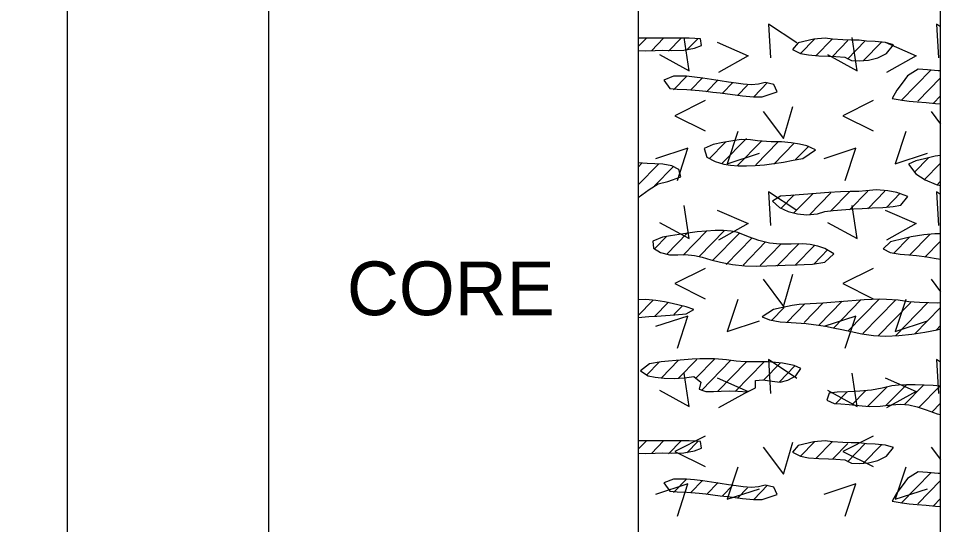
# Model space of a CAD drawing. Extents: x 0 to 0.833, y -0.323 to 0.608.
# Drawn here: x 0.719 to 0.8333, y -0.1987 to -0.1358 of the extents above; entities that cross this region are included whole.
import ezdxf

# ---------------------------------------------------------------- set-up
doc = ezdxf.new("R2010")
doc.units = 0

msp = doc.modelspace()

# ---------------------------------------------------------------- linework, layer by layer
for points in [[(0, -0.32328), (0.83333, -0.32328), (0.83333, 0.60833), (0, 0.60833)], [(0.79583, -0.13982), (0.79676, -0.13983), (0.79792, -0.13981), (0.79882, -0.13977), (0.79992, -0.13982), (0.80151, -0.13977), (0.80282, -0.13952), (0.80367, -0.1392), (0.80354, -0.13836), (0.80216, -0.13827), (0.79583, -0.13827)], [(0.81822, -0.14047), (0.81944, -0.14052), (0.82033, -0.14056), (0.82145, -0.14063), (0.82229, -0.14105), (0.82324, -0.14109), (0.82438, -0.14099), (0.82555, -0.1407), (0.82662, -0.14019), (0.82749, -0.1391), (0.82651, -0.13879), (0.82524, -0.13869), (0.82413, -0.13863), (0.82324, -0.13852), (0.82226, -0.1385), (0.82121, -0.13848), (0.81995, -0.13839), (0.81902, -0.13827), (0.81761, -0.13841), (0.81566, -0.13885), (0.81496, -0.13969), (0.81598, -0.14018), (0.81695, -0.14036)], [(0.83305, -0.14232), (0.83171, -0.14221), (0.83054, -0.14211), (0.82925, -0.14293), (0.82857, -0.14384), (0.82792, -0.14473), (0.82735, -0.14575), (0.82858, -0.14598), (0.82945, -0.14608), (0.83045, -0.14618), (0.83155, -0.14627), (0.83272, -0.14637), (0.83333, -0.14642), (0.83333, -0.14233)], [(0.80066, -0.14462), (0.80188, -0.14463), (0.80339, -0.14476), (0.80423, -0.14485), (0.8051, -0.14496), (0.806, -0.14508), (0.80692, -0.1452), (0.80784, -0.14532), (0.80875, -0.14543), (0.81014, -0.14557), (0.81119, -0.14556), (0.81222, -0.14522), (0.81308, -0.14493), (0.81267, -0.14403), (0.8116, -0.14378), (0.81075, -0.14398), (0.80989, -0.14406), (0.80885, -0.14398), (0.80799, -0.14387), (0.80703, -0.14373), (0.806, -0.14356), (0.80492, -0.1434), (0.80384, -0.14324), (0.8028, -0.14311), (0.80182, -0.14301), (0.8002, -0.14301), (0.79901, -0.14348), (0.79974, -0.14452)], [(0.81233, -0.15113), (0.81063, -0.15101), (0.80977, -0.15088), (0.8086, -0.15087), (0.80755, -0.15101), (0.80632, -0.15121), (0.80513, -0.15146), (0.80403, -0.15198), (0.80436, -0.15304), (0.80536, -0.1536), (0.80647, -0.1539), (0.8073, -0.15405), (0.80824, -0.15413), (0.80926, -0.15414), (0.81035, -0.15409), (0.81149, -0.15398), (0.81267, -0.15384), (0.81386, -0.15365), (0.81506, -0.15344), (0.81625, -0.15321), (0.81783, -0.15213), (0.81673, -0.15163), (0.81585, -0.15142), (0.8148, -0.15127), (0.81361, -0.15116)], [(0.83265, -0.15294), (0.83136, -0.15325), (0.83028, -0.15352), (0.82934, -0.15392), (0.83026, -0.15512), (0.83142, -0.15588), (0.83279, -0.15646), (0.83333, -0.15656), (0.83333, -0.15285)], [(0.79583, -0.15804), (0.79719, -0.15705), (0.79831, -0.15635), (0.79951, -0.15607), (0.80111, -0.15547), (0.80086, -0.15459), (0.80002, -0.15411), (0.79889, -0.15392), (0.79791, -0.15389), (0.79694, -0.15383), (0.79583, -0.15375)], [(0.82537, -0.15709), (0.82408, -0.15724), (0.82319, -0.1573), (0.82214, -0.15732), (0.82091, -0.15736), (0.81947, -0.15745), (0.81792, -0.15757), (0.81632, -0.15769), (0.81475, -0.15779), (0.81348, -0.15789), (0.81247, -0.15853), (0.81337, -0.15929), (0.81444, -0.15979), (0.81561, -0.16008), (0.81675, -0.16019), (0.81807, -0.16007), (0.81896, -0.1598), (0.82003, -0.15965), (0.82157, -0.15953), (0.82253, -0.15947), (0.82362, -0.15942), (0.82483, -0.15935), (0.82618, -0.15929), (0.82745, -0.15918), (0.82842, -0.159), (0.82927, -0.15795), (0.82791, -0.15743), (0.82679, -0.15723)], [(0.79885, -0.163), (0.79763, -0.16346), (0.79773, -0.16436), (0.79859, -0.16488), (0.7997, -0.16518), (0.80074, -0.16517), (0.80165, -0.16515), (0.80281, -0.16524), (0.80377, -0.16545), (0.80486, -0.1658), (0.80606, -0.16609), (0.80751, -0.16637), (0.80905, -0.16655), (0.81052, -0.16658), (0.81177, -0.16652), (0.81289, -0.16648), (0.81408, -0.16645), (0.81553, -0.16641), (0.81642, -0.16638), (0.81745, -0.16635), (0.81897, -0.16608), (0.82011, -0.16504), (0.81896, -0.16437), (0.8181, -0.16411), (0.81717, -0.16391), (0.81626, -0.1638), (0.81479, -0.16386), (0.81343, -0.16386), (0.8121, -0.16371), (0.8108, -0.16341), (0.80953, -0.16295), (0.8082, -0.1624), (0.80736, -0.16224), (0.8064, -0.16216), (0.80536, -0.16216), (0.80427, -0.16222), (0.80314, -0.16233), (0.80201, -0.16248), (0.8009, -0.16264), (0.79984, -0.16282)], [(0.83263, -0.16256), (0.83126, -0.16269), (0.82969, -0.16296), (0.82883, -0.16313), (0.82712, -0.16354), (0.82623, -0.16441), (0.82708, -0.1649), (0.82831, -0.16509), (0.82941, -0.16516), (0.83033, -0.16524), (0.83165, -0.16543), (0.83253, -0.16557), (0.83333, -0.16571), (0.83333, -0.16256)], [(0.79583, -0.17296), (0.79715, -0.17285), (0.79814, -0.17278), (0.79922, -0.1727), (0.80039, -0.17261), (0.80179, -0.17249), (0.80275, -0.17198), (0.80179, -0.17164), (0.80091, -0.17142), (0.80003, -0.1712), (0.79909, -0.17099), (0.79803, -0.17083), (0.79677, -0.17073), (0.79583, -0.17075)], [(0.82816, -0.17521), (0.82978, -0.17504), (0.83137, -0.17479), (0.8329, -0.17447), (0.83333, -0.17437), (0.83333, -0.17113), (0.83295, -0.17116), (0.83188, -0.17114), (0.83071, -0.17109), (0.82938, -0.17099), (0.82807, -0.17082), (0.82662, -0.1707), (0.82576, -0.17069), (0.82484, -0.17072), (0.82387, -0.17077), (0.82286, -0.17084), (0.82182, -0.17092), (0.82077, -0.171), (0.81973, -0.17109), (0.81872, -0.17116), (0.81715, -0.17126), (0.81579, -0.17135), (0.81491, -0.17148), (0.81357, -0.17176), (0.8126, -0.17197), (0.81121, -0.17289), (0.8121, -0.17325), (0.81345, -0.1735), (0.81479, -0.17359), (0.81668, -0.17369), (0.81818, -0.17389), (0.81905, -0.17404), (0.82, -0.17422), (0.82107, -0.17443), (0.82225, -0.17468), (0.82357, -0.17497), (0.82501, -0.1752), (0.82656, -0.17527)], [(0.79708, -0.18019), (0.79794, -0.18037), (0.79904, -0.18048), (0.80028, -0.18051), (0.80156, -0.18046), (0.80274, -0.1803), (0.80361, -0.18097), (0.80338, -0.18186), (0.80422, -0.18213), (0.80517, -0.18215), (0.80613, -0.1821), (0.8072, -0.18206), (0.80818, -0.1821), (0.80939, -0.18217), (0.81037, -0.1817), (0.81038, -0.18076), (0.8113, -0.18069), (0.81244, -0.18088), (0.81346, -0.18099), (0.81438, -0.18073), (0.81539, -0.18019), (0.81601, -0.17928), (0.81517, -0.1789), (0.81374, -0.17863), (0.81285, -0.17853), (0.81187, -0.17848), (0.81, -0.17847), (0.8091, -0.17846), (0.808, -0.17838), (0.80678, -0.17823), (0.8053, -0.1781), (0.80443, -0.17808), (0.80349, -0.1781), (0.80251, -0.17814), (0.80152, -0.1782), (0.80054, -0.17828), (0.79959, -0.17837), (0.7987, -0.17847), (0.79722, -0.17869), (0.79614, -0.17957)], [(0.83241, -0.18141), (0.83129, -0.18134), (0.83017, -0.18131), (0.8291, -0.1813), (0.82811, -0.18134), (0.82728, -0.18143), (0.82608, -0.18173), (0.82476, -0.18196), (0.8233, -0.18209), (0.82183, -0.18218), (0.82051, -0.18224), (0.81951, -0.18233), (0.81922, -0.1832), (0.82013, -0.18362), (0.82097, -0.18367), (0.822, -0.18377), (0.82318, -0.1839), (0.82448, -0.18399), (0.82584, -0.18396), (0.82719, -0.1838), (0.82836, -0.18373), (0.8294, -0.18381), (0.83043, -0.18404), (0.83156, -0.18444), (0.83291, -0.18493), (0.83333, -0.185), (0.83333, -0.18148)], [(0.79583, -0.18982), (0.79676, -0.18983), (0.79792, -0.18981), (0.79882, -0.18977), (0.79992, -0.18982), (0.80151, -0.18977), (0.80282, -0.18952), (0.80367, -0.1892), (0.80354, -0.18836), (0.80216, -0.18827), (0.79583, -0.18827)], [(0.81822, -0.19047), (0.81944, -0.19052), (0.82033, -0.19056), (0.82145, -0.19063), (0.82229, -0.19105), (0.82324, -0.19109), (0.82438, -0.19099), (0.82555, -0.1907), (0.82662, -0.19019), (0.82749, -0.1891), (0.82651, -0.18879), (0.82524, -0.18869), (0.82413, -0.18863), (0.82324, -0.18852), (0.82226, -0.1885), (0.82121, -0.18848), (0.81995, -0.18839), (0.81902, -0.18827), (0.81761, -0.18841), (0.81566, -0.18885), (0.81496, -0.18969), (0.81598, -0.19018), (0.81695, -0.19036)], [(0.83305, -0.19232), (0.83171, -0.19221), (0.83054, -0.19211), (0.82925, -0.19293), (0.82857, -0.19384), (0.82792, -0.19473), (0.82735, -0.19575), (0.82858, -0.19598), (0.82945, -0.19608), (0.83045, -0.19618), (0.83155, -0.19627), (0.83272, -0.19637), (0.83333, -0.19642), (0.83333, -0.19233)], [(0.80066, -0.19462), (0.80188, -0.19463), (0.80339, -0.19476), (0.80423, -0.19485), (0.8051, -0.19496), (0.806, -0.19508), (0.80692, -0.1952), (0.80784, -0.19532), (0.80875, -0.19543), (0.81014, -0.19557), (0.81119, -0.19556), (0.81222, -0.19522), (0.81308, -0.19493), (0.81267, -0.19403), (0.8116, -0.19378), (0.81075, -0.19398), (0.80989, -0.19406), (0.80885, -0.19398), (0.80799, -0.19387), (0.80703, -0.19373), (0.806, -0.19356), (0.80492, -0.1934), (0.80384, -0.19324), (0.8028, -0.19311), (0.80182, -0.19301), (0.8002, -0.19301), (0.79901, -0.19348), (0.79974, -0.19452)]]:
    msp.add_lwpolyline(points, close=True)
for points in [[(0.725, 0.55417), (0.725, -0.28575)], [(0.75, 0.55417), (0.75, -0.28575)], [(0.75, 0.55417), (0.75, -0.28575)], [(0.79583, 0.55417), (0.79583, -0.28575)], [(0.725, 0.54167), (0.725, -0.28575)], [(0.83333, -0.28575), (0.83333, 0.50165)], [(0.81551, -0.13884), (0.81201, -0.13653), (0.81226, -0.14071)], [(0.83333, -0.13685), (0.83284, -0.13653), (0.83309, -0.14071)], [(0.79583, -0.1393), (0.79681, -0.1383)], [(0.79898, -0.13828), (0.79747, -0.13983)], [(0.79847, -0.14032), (0.80215, -0.14232), (0.80153, -0.1382)], [(0.80116, -0.13827), (0.79959, -0.13987)], [(0.80328, -0.13831), (0.80188, -0.13974)], [(0.8193, -0.14032), (0.82299, -0.14232), (0.82236, -0.1382)], [(0.80562, -0.13878), (0.80946, -0.14046), (0.80581, -0.14252)], [(0.8177, -0.13841), (0.81596, -0.14019)], [(0.81988, -0.13839), (0.81785, -0.14047)], [(0.82185, -0.13858), (0.81997, -0.14051)], [(0.824, -0.13859), (0.82178, -0.14087)], [(0.82601, -0.13875), (0.82378, -0.14103)], [(0.82645, -0.13878), (0.83029, -0.14046), (0.82664, -0.14252)], [(0.83217, -0.14219), (0.82844, -0.14601)], [(0.80188, -0.14297), (0.8002, -0.14469)], [(0.8038, -0.14321), (0.80237, -0.14467)], [(0.80575, -0.14343), (0.80429, -0.14492)], [(0.80758, -0.14376), (0.80627, -0.14511)], [(0.81188, -0.14378), (0.81016, -0.14554)], [(0.83333, -0.14321), (0.83052, -0.14609)], [(0.80941, -0.1441), (0.80816, -0.14538)], [(0.80412, -0.14603), (0.80038, -0.14791), (0.80412, -0.14978)], [(0.82496, -0.14603), (0.82121, -0.14791), (0.82496, -0.14978)], [(0.83333, -0.14543), (0.83245, -0.14633)], [(0.81134, -0.14738), (0.81384, -0.15075), (0.81503, -0.14675)], [(0.83217, -0.14738), (0.83333, -0.14894)], [(0.80626, -0.15381), (0.80928, -0.15071)], [(0.80818, -0.14987), (0.80687, -0.15387), (0.81087, -0.15255)], [(0.82901, -0.14987), (0.8277, -0.15387), (0.8317, -0.15255)], [(0.80069, -0.15595), (0.802, -0.15195), (0.798, -0.15326)], [(0.80465, -0.15324), (0.80667, -0.15117)], [(0.80809, -0.15414), (0.81111, -0.15105)], [(0.81041, -0.15398), (0.81318, -0.15115)], [(0.81264, -0.1539), (0.81518, -0.1513)], [(0.81536, -0.15333), (0.81699, -0.15167)], [(0.82152, -0.15595), (0.82284, -0.15195), (0.81884, -0.15326)], [(0.8301, -0.15491), (0.83184, -0.15312)], [(0.7963, -0.15379), (0.79583, -0.15427)], [(0.79834, -0.15392), (0.79583, -0.15649)], [(0.79786, -0.15662), (0.80023, -0.15419)], [(0.83131, -0.15588), (0.83333, -0.15381)], [(0.83285, -0.15651), (0.83333, -0.15602)], [(0.81551, -0.15967), (0.81201, -0.15736), (0.81226, -0.16155)], [(0.81519, -0.15772), (0.81354, -0.15942)], [(0.81514, -0.15998), (0.81748, -0.15759)], [(0.81709, -0.1602), (0.81974, -0.15749)], [(0.8197, -0.15975), (0.82203, -0.15735)], [(0.82202, -0.15958), (0.8243, -0.15725)], [(0.82431, -0.15945), (0.82644, -0.15726)], [(0.82663, -0.15928), (0.82834, -0.15753)], [(0.83333, -0.15768), (0.83284, -0.15736), (0.83309, -0.16155)], [(0.79847, -0.16116), (0.80215, -0.16316), (0.80153, -0.15903)], [(0.80562, -0.15961), (0.80946, -0.16129), (0.80581, -0.16336)], [(0.8193, -0.16116), (0.82299, -0.16316), (0.82236, -0.15903)], [(0.82645, -0.15961), (0.83029, -0.16129), (0.82664, -0.16336)], [(0.80142, -0.1652), (0.8043, -0.16225)], [(0.80653, -0.16217), (0.8034, -0.16539)], [(0.79938, -0.16287), (0.79786, -0.16442)], [(0.79933, -0.16513), (0.80195, -0.16244)], [(0.80506, -0.16589), (0.8084, -0.16247)], [(0.80997, -0.16307), (0.80675, -0.16638)], [(0.82751, -0.16502), (0.82945, -0.16303)], [(0.83203, -0.16261), (0.82949, -0.16521)], [(0.83138, -0.16548), (0.83333, -0.16348)], [(0.81164, -0.16358), (0.80884, -0.16644)], [(0.81353, -0.16386), (0.81094, -0.16651)], [(0.81303, -0.16658), (0.81579, -0.16375)], [(0.81534, -0.16642), (0.81768, -0.16402)], [(0.8176, -0.16632), (0.81934, -0.16453)], [(0.83333, -0.1657), (0.83333, -0.16569)], [(0.80412, -0.16687), (0.80038, -0.16874), (0.80412, -0.17062)], [(0.82496, -0.16687), (0.82121, -0.16874), (0.82496, -0.17062)], [(0.81134, -0.16821), (0.81384, -0.17158), (0.81503, -0.16758)], [(0.83217, -0.16821), (0.83333, -0.16977)], [(0.79765, -0.17085), (0.79583, -0.17271)], [(0.7996, -0.17106), (0.79786, -0.17284)], [(0.80818, -0.1707), (0.80687, -0.1747), (0.81087, -0.17339)], [(0.8143, -0.17352), (0.8165, -0.17127)], [(0.8164, -0.17359), (0.81879, -0.17114)], [(0.81829, -0.17387), (0.82114, -0.17094)], [(0.82004, -0.17429), (0.82346, -0.17078)], [(0.82569, -0.1707), (0.82184, -0.17465)], [(0.82775, -0.1708), (0.8237, -0.17495)], [(0.82964, -0.17108), (0.82557, -0.17526)], [(0.82901, -0.1707), (0.8277, -0.1747), (0.8317, -0.17339)], [(0.83173, -0.17115), (0.82774, -0.17524)], [(0.8013, -0.17154), (0.80027, -0.17259)], [(0.81392, -0.1717), (0.81235, -0.17331)], [(0.83333, -0.17173), (0.83012, -0.17502)], [(0.80069, -0.17678), (0.802, -0.17278), (0.798, -0.17409)], [(0.82152, -0.17678), (0.82284, -0.17278), (0.81884, -0.17409)], [(0.83281, -0.17447), (0.83333, -0.17394)], [(0.79871, -0.18045), (0.80085, -0.17825)], [(0.80083, -0.18049), (0.80311, -0.17815)], [(0.80534, -0.17807), (0.80299, -0.18049)], [(0.80367, -0.182), (0.80732, -0.17826)], [(0.81551, -0.18051), (0.81201, -0.17819), (0.81226, -0.18238)], [(0.83333, -0.17852), (0.83284, -0.17819), (0.83309, -0.18238)], [(0.79844, -0.17851), (0.79691, -0.18008)], [(0.80571, -0.18212), (0.80924, -0.17851)], [(0.81142, -0.17849), (0.80785, -0.18214)], [(0.81141, -0.18071), (0.81348, -0.17859)], [(0.81528, -0.17895), (0.81331, -0.18097)], [(0.79847, -0.18199), (0.80215, -0.18399), (0.80153, -0.17986)], [(0.80562, -0.18044), (0.80946, -0.18213), (0.80581, -0.18419)], [(0.8193, -0.18199), (0.82299, -0.18399), (0.82236, -0.17986)], [(0.82645, -0.18044), (0.83029, -0.18213), (0.82664, -0.18419)], [(0.82433, -0.18398), (0.82666, -0.18159)], [(0.82909, -0.1813), (0.82656, -0.1839)], [(0.82885, -0.18377), (0.83122, -0.18134)], [(0.83325, -0.18148), (0.83065, -0.18413)], [(0.82035, -0.18363), (0.82176, -0.18218)], [(0.82233, -0.18381), (0.82408, -0.18202)], [(0.83333, -0.1836), (0.83227, -0.18469)], [(0.79583, -0.1893), (0.79681, -0.1883)], [(0.79898, -0.18828), (0.79747, -0.18983)], [(0.80116, -0.18827), (0.79959, -0.18987)], [(0.80412, -0.1877), (0.80038, -0.18958), (0.80412, -0.19145)], [(0.80328, -0.18831), (0.80188, -0.18974)], [(0.81134, -0.18904), (0.81384, -0.19242), (0.81503, -0.18842)], [(0.8177, -0.18841), (0.81596, -0.19019)], [(0.81988, -0.18839), (0.81785, -0.19047)], [(0.82185, -0.18858), (0.81997, -0.19051)], [(0.82496, -0.1877), (0.82121, -0.18958), (0.82496, -0.19145)], [(0.824, -0.18859), (0.82178, -0.19087)], [(0.82601, -0.18875), (0.82378, -0.19103)], [(0.83217, -0.18904), (0.83333, -0.1906)], [(0.80818, -0.19153), (0.80687, -0.19553), (0.81087, -0.19422)], [(0.82901, -0.19153), (0.8277, -0.19553), (0.8317, -0.19422)], [(0.80188, -0.19297), (0.8002, -0.19469)], [(0.8038, -0.19321), (0.80237, -0.19467)], [(0.83217, -0.19219), (0.82844, -0.19601)], [(0.83333, -0.19321), (0.83052, -0.19609)], [(0.80069, -0.19761), (0.802, -0.19361), (0.798, -0.19493)], [(0.80575, -0.19343), (0.80429, -0.19492)], [(0.80758, -0.19376), (0.80627, -0.19511)], [(0.80941, -0.19409), (0.80816, -0.19538)], [(0.81188, -0.19378), (0.81016, -0.19554)], [(0.82152, -0.19761), (0.82284, -0.19361), (0.81884, -0.19493)], [(0.83333, -0.19543), (0.83245, -0.19633)]]:
    msp.add_lwpolyline(points)

# ---------------------------------------------------------------- texts
msp.add_text('CORE', height=0.006667).set_placement((0.75971, -0.17267))

doc.saveas('drawing.dxf')
